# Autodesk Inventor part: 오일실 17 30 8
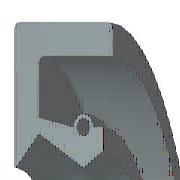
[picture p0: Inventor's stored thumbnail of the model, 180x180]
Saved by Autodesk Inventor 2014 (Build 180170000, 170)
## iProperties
Created: 2012-02
Part Number: 오일실 17 30 8
Material: 고무
Description: 오일-실
Document SubType Name: Modeling
Standard: KS B 2804
Designer: mduedu
Standards Organization: KS
Language: ko-KR
Size Designation: D - 17 30 8
Categories: <MemberInstance><Categories><Category DisplayName="샤프트 부품" InternalName="7f7aeb1f-a693-4053-b835-cee3144e0d98" Mnemonic="SHFT"><Category DisplayName="실링" Intern
Density: 0.93 g/cm^3
Mass: 2.05797 g
Surface Area: 29.3036 cm^2
Volume: 2.21288 cm^3
Appearance: 고무 - 검은색 - 버전 1.1
IsCustomPart: 1
Author: mduedu
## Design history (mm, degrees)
revolve "본체" stored, may be unused: angle "d17" = 90 deg
revolve "스프링1" stored, may be unused: angle "d18" = 90 deg
body "Solid1"
sketch "스케치1"
  geometry: L1 (0, 15)-(8, 15); L2 (8, 13.25)-(1.75, 13.25); L3 (1.75, 10.25)-(4.9, 8.5); L4 (4.9, 8.5)-(0, 8.5); L5 (0, 0)-(9.586, 0) reference; L6 (4.9, 8.5)-(6.3, 9.375); L7 (0, 18)-(0, -3) reference; L8 (-1.941, 0)-(11.507, 0) reference; L9 (4.2, 10.6)-(1.75, 11.21); L10 (1.75, 11.21)-(1.75, 13.25); L11 (0, 15)-(0, 8.588); L12 (4.9, 8.5)-(0, 8.5); L13 (1.75, 10.25)-(0.152, 8.528); L14 (8, 15)-(8, 13.25); L15 (5.6, 10.6)-(6.3, 10.6); L16 (6.3, 10.6)-(6.3, 9.375); C1 r 0.455 at (4.9, 10.6); A1 r 0.7 centre (4.9, 10.6) between (5.6, 10.6) and (4.2, 10.6); A2 r 0.088 centre (0.088, 8.588) between (0, 8.588) and (0.152, 8.528); 1 further point
  constraints: 28 end point, 5 horizontal alignment, 5 point on line, 4 point on circle, 4 vertical alignment, 3 centre point, 3 tangent, 2 collinear, 2 horizontal, 2 perpendicular, 1 coincident, 1 parallel
  dimensions: "d0" = 30 diameter of L1 L5 (= SD2); "d1" = 1.75 distance of L1.end L2.start (= SD); "d2" = 0.91 diameter of C1 (= SPDI); "d3" = 1.4 diameter of A1 (= SPDA); "d4" = 17 diameter of L3.end L5 (= NND); "d5" = 20.5 diameter of L3.start L5 (= TKDM); "d7" = 22.42 diameter of L9.end L5 (= TKDM + 0.24 x SWDT); "d8" = 1.75 distance between parallel lines of L11 L10 (= SD); "d9" = 4.9 distance from line of L11 C1.centre (= SPDST); "d10" = 21.2 diameter of C1.centre L5 (= HLDM); "d11" = 0.0875 radius of A2 (= 0.25 x LAB); "d12" = 6.3 distance between parallel lines of L11 L16 (= SDI); "d13" = 18.75 diameter of L6.end L5 (= ABDM); "d14" = 8 distance from line of L11 L1.end (= SWDT)
fillet "모깎기1" dims "d6" = 0.3 (= RR)
other parameters: "SD2" = 30 [user parameter; used in 1 equation term], "SWDT" = 8 [user parameter; used in 2 equation terms], "RR" = 0.3 [user parameter; used in 1 equation term], "SD" = 1.75 [user parameter; used in 2 equation terms], "NND" = 17 [user parameter; used in 1 equation term], "SPDA" = 1.4 [user parameter; used in 1 equation term], "SPDI" = 0.91 [user parameter; used in 1 equation term], "TKDM" = 20.5 [user parameter; used in 2 equation terms], "HLDM" = 21.2 [user parameter; used in 1 equation term], "ABDM" = 18.75 [user parameter; used in 1 equation term], "SDI" = 6.3 [user parameter; used in 1 equation term], "SPDST" = 4.9 [user parameter; used in 1 equation term], "LAB" = 0.35 [user parameter; used in 1 equation term], "d15" = 0, "d16" = 0, "d19" = 0
